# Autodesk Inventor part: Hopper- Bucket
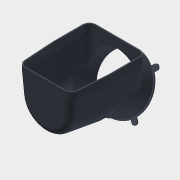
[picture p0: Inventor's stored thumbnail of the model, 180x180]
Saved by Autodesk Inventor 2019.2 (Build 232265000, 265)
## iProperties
Created: 2005-11
Part Number: Hopper- Bucket
Document SubType Name: Modeling
Designer: floress
Material: Default
Density: 1 g/cm^3
Appearance: Dark Gray
Author: floress
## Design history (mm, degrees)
workplane "Work Plane1"
sketch "Sketch2"
  geometry: C1 r 73.025 at (8.648, 3.854)
  constraints: 1 centre point
extrude "Extrusion1" new body sketch "Sketch2" distance "d4" = 76.2; taper "d5" = 0 deg
workplane "Work Plane7"
sketch "Sketch9"
  geometry: L1 (-80.012, -213.714)-(79.377, -213.714); L2 (-80.012, -213.714)-(-80.012, -187.536); L3 (-80.012, -187.536)-(-72.976, -126.933); L4 (-0.318, -133.26)-(-0.318, -165.203); L5 (79.377, -213.714)-(79.377, -187.536); L6 (79.377, -187.536)-(72.341, -126.933); L7 (-72.976, -126.933)-(72.341, -126.933); 1 further point; 1 other entity
  constraints: 14 end point, 2 horizontal, 2 symmetric about line, 1 midpoint, 1 parallel, 1 perpendicular, 1 vertical alignment, 3 other
extrude "Extrusion3" join sketch "Sketch9" stored distance "d22" = 101.6; taper "d23" = 0 deg
workplane "Work Plane8"
sketch "Sketch10"
  geometry: L1 (-213.714, -80.012)-(-213.714, 79.377) reference; L2 (-213.714, -73.343)-(-213.714, 72.707); L3 (-213.714, 72.707)-(-194.664, 72.707); L4 (-187.536, 79.377)-(-126.933, 72.341) reference; L5 (-194.664, 72.707)-(-144.203, 66.849); L6 (-213.714, -73.343)-(-194.664, -73.343); L7 (-194.664, -73.343)-(-144.203, -67.485); A1 r 67.618 centre (-152.001, -0.318) between (-144.203, -67.485) and (-144.203, 66.849); 2 further points
  constraints: 10 end point, 2 midpoint, 2 point on circle, 2 vertical alignment, 1 centre point, 1 collinear, 1 horizontal, 1 horizontal alignment, 1 parallel, 1 perpendicular, 1 tangent, 2 other
  dimensions: "d25" = 146.05 distance between parallel lines of L3 L6; "d26" = 50.8 distance of L6.end L7.end; "d27" = 19.05 distance of L2.start L6.end
loft "Loft2" sketch "Sketch10" dims "d28" = 0, "d29" = 90 deg, "d30" = 0, "d31" = 90 deg
  node "Edges1"
shell "Shell1" dims "d33" = 3.175
fillet "Fillet4" dims "d34" = 15.875
fillet "Fillet5" dims "d35" = 19.05
workplane "Work Plane9"
sketch "Sketch11"
  geometry: L1 (-45.233, 68.075)-(-39.815, 62.657) reference; L2 (-50.154, 52.318)-(-55.572, 57.736) reference; L3 (-55.572, -50.027)-(-50.154, -44.609) reference; L4 (-39.815, -54.948)-(-45.233, -60.366) reference; L5 (62.53, -60.366)-(57.112, -54.948) reference; L6 (67.451, -44.609)-(72.869, -50.027) reference; L7 (41.269, 80.807)-(38.752, 73.856) reference; L8 (24.817, 78.319)-(27.522, 85.787) reference; L9 (67.451, -44.609)-(65.195, -42.353); L10 (38.752, 73.856)-(37.668, 70.866); C1 r 1.651 at (-50.403, 62.906) reference; C2 r 1.651 at (34.396, 83.297) reference; C3 r 1.651 at (-50.403, -55.197) reference; C4 r 1.651 at (67.699, -55.197) reference; A1 r 7.311 centre (-50.403, 62.906) between (-45.233, 68.075) and (-55.572, 57.736) reference; A2 r 76.2 centre (8.648, 3.854) between (-50.154, 52.318) and (-50.154, -44.609) reference; A3 r 7.311 centre (-50.403, -55.197) between (-55.572, -50.027) and (-45.233, -60.366) reference; A4 r 76.2 centre (8.648, 3.854) between (-39.815, -54.948) and (57.112, -54.948) reference; A5 r 7.311 centre (67.699, -55.197) between (62.53, -60.366) and (72.869, -50.027) reference; A6 r 76.2 centre (8.648, 3.854) between (67.451, -44.609) and (84.776, 0.541) reference; A7 r 3.175 centre (81.604, 0.679) between (84.776, 0.541) and (78.432, 0.817) reference; A8 r 69.85 centre (8.648, 3.854) between (40.301, 66.121) and (78.432, 0.817) reference; A9 r 3.175 centre (41.74, 68.951) between (40.301, 66.121) and (43.179, 71.781) reference; A10 r 76.2 centre (8.648, 3.854) between (43.179, 71.781) and (38.752, 73.856) reference; A11 r 7.311 centre (34.396, 83.297) between (41.269, 80.807) and (27.522, 85.787) reference; A12 r 76.2 centre (8.648, 3.854) between (24.817, 78.319) and (-39.815, 62.657) reference; A13 r 73.025 centre (8.648, 3.854) between (65.195, -42.353) and (37.668, 70.866) reference
  constraints: 4 end point, 2 point on circle, 1 collinear, 1 parallel
extrude "Extrusion4" join sketch "Sketch11" distance "d36" = 3.175; taper "d37" = 0 deg
sketch "Sketch12"
  geometry: L1 (99.908, -213.714)-(17.462, -213.714) reference; C1 r 1.524 at (92.428, -191.489)
  constraints: 1 centre point
  dimensions: "d38" = 3.048 diameter of C1; "d39" = 22.225 distance from line of L1 C1.centre
extrude "Extrusion5" cut sketch "Sketch12" extent not by distance; stored distance "d40" = 25.4; taper "d41" = 0 deg
body "Solid1"
node "Reference2"
other parameters: "d21" = -49.2125, "d24" = 101.6
